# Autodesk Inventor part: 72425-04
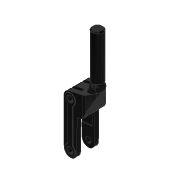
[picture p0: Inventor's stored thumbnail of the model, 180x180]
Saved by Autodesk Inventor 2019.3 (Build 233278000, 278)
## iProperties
Created: 2012-10
Part Number: 72425-04
Material: Ogólny
Document SubType Name: Modeling
Designer: CADENGINEERING4
Density: 1 g/cm^3
Appearance: Gładki — czarny
Author: CADENGINEERING4
Revision Number: ÈÎºÎ
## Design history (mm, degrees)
feature "ÊäÈë1"
node "Bryła1"
